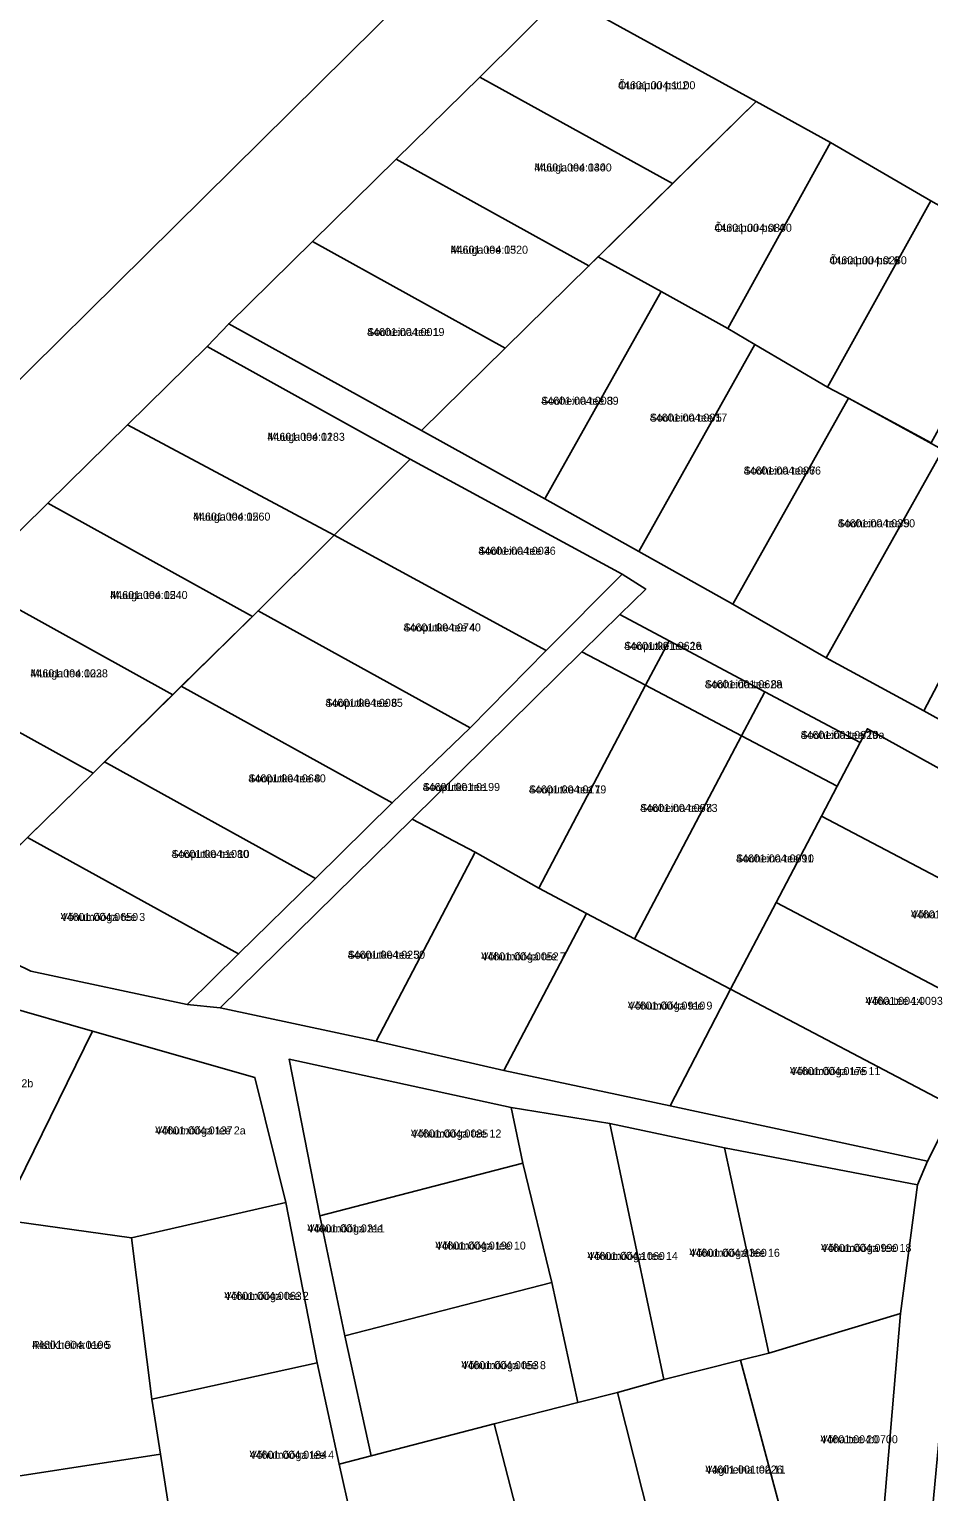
# Model space of a CAD drawing. Extents: x 551843 to 558501, y 6589003 to 6595718.
# Drawn here: x 552032.7 to 552201.2, y 6593331.6 to 6593605.7 of the extents above; entities that cross this region are included whole.
import ezdxf

# ---------------------------------------------------------------- set-up
doc = ezdxf.new("R2010")
doc.units = 0
for name, color, linetype in [('L_AADRESS', 7, 'Continuous'), ('PIIR', 7, 'Continuous'), ('TUNNUS', 7, 'Continuous')]:
    doc.layers.add(name, color=color, linetype=linetype)

msp = doc.modelspace()

# ---------------------------------------------------------------- linework, layer by layer
at = {"layer": 'PIIR'}
for points in [[(551957.32, 6593467.43), (552124.69, 6593632.88)], [(552132.56, 6593612.13), (552117.1, 6593596.73), (552101.41, 6593581.32), (552085.73, 6593565.91), (552070.04, 6593550.5), (552066, 6593546.24), (552051.07, 6593531.56), (552036.12, 6593516.88), (552021.18, 6593502.19)], [(552390.85, 6593469.35), (552373.17, 6593479.39), (552355.46, 6593489.1), (552337.59, 6593498.96), (552319.2, 6593509.13), (552282.48, 6593529.37), (552274.21, 6593533.45), (552239.65, 6593552.36), (552220.64, 6593562.81), (552201.61, 6593573.54), (552182.84, 6593584.46), (552168.9, 6593592.16), (552132.56, 6593612.13)], [(552231.31, 6593451.62), (552189.74, 6593474.62), (552188.39, 6593472.05), (552170.52, 6593481.56), (552152.58, 6593491.11), (552143.33, 6593496.01), (552148.19, 6593500.8), (552143.77, 6593503.59), (552104.07, 6593525.15), (552066, 6593546.24), (552070.04, 6593550.5), (552106.16, 6593530.52), (552129.28, 6593517.7), (552146.87, 6593507.81), (552164.48, 6593497.95), (552181.99, 6593487.89), (552200.28, 6593477.95), (552234.92, 6593458.82)], [(552015.51, 6593437.71), (552032.93, 6593429.18), (552062.25, 6593422.95), (552068.43, 6593422.31), (552097.65, 6593416.1), (552121.62, 6593410.61), (552152.74, 6593403.96), (552200.97, 6593393.62), (552199.1, 6593389.17), (552162.95, 6593396.07), (552141.49, 6593400.62), (552122.94, 6593403.65), (552081.34, 6593412.69), (552087.1, 6593383.34), (552091.81, 6593360.84), (552096.7, 6593338.37), (552090.74, 6593336.83), (552086.62, 6593355.81), (552080.74, 6593385.84), (552074.9, 6593409.27), (552044.52, 6593417.97), (552027.57, 6593422.82)]]:
    msp.add_lwpolyline(points, dxfattribs=at)
for points in [[(552153.22, 6593576.76), (552117.1, 6593596.73), (552132.56, 6593612.13), (552168.9, 6593592.16)], [(552117.1, 6593596.73), (552153.22, 6593576.76), (552137.53, 6593561.35), (552101.41, 6593581.32)], [(552182.84, 6593584.46), (552163.6, 6593549.62), (552151.05, 6593556.56), (552139.29, 6593563.05), (552168.9, 6593592.16)], [(552201.61, 6593573.54), (552182.26, 6593538.65), (552168.62, 6593546.63), (552163.6, 6593549.62), (552182.84, 6593584.46)], [(552101.41, 6593581.32), (552137.53, 6593561.35), (552121.85, 6593545.95), (552085.73, 6593565.91)], [(552220.64, 6593562.81), (552201.67, 6593528.18), (552186.19, 6593536.59), (552182.26, 6593538.65), (552201.61, 6593573.54)], [(552121.85, 6593545.95), (552106.16, 6593530.52), (552070.04, 6593550.5), (552085.73, 6593565.91)], [(552139.29, 6593563.05), (552151.05, 6593556.56), (552129.28, 6593517.7), (552106.16, 6593530.52), (552121.85, 6593545.95), (552137.53, 6593561.35)], [(552168.62, 6593546.63), (552146.87, 6593507.81), (552129.28, 6593517.7), (552151.05, 6593556.56), (552163.6, 6593549.62)], [(552104.07, 6593525.15), (552089.77, 6593510.89), (552051.07, 6593531.56), (552066, 6593546.24)], [(552168.62, 6593546.63), (552182.26, 6593538.65), (552186.19, 6593536.59), (552164.48, 6593497.95), (552146.87, 6593507.81)], [(552164.48, 6593497.95), (552186.19, 6593536.59), (552203.84, 6593526.91), (552181.99, 6593487.89)], [(552051.07, 6593531.56), (552089.77, 6593510.89), (552074.48, 6593495.68), (552036.12, 6593516.88)], [(552220.89, 6593516.92), (552219.98, 6593515.24), (552210.12, 6593496.62), (552200.28, 6593477.95), (552181.99, 6593487.89), (552203.84, 6593526.91)], [(552143.77, 6593503.59), (552129.55, 6593489.29), (552089.77, 6593510.89), (552104.07, 6593525.15)], [(552036.12, 6593516.88), (552074.48, 6593495.68), (552059.54, 6593480.99), (552021.18, 6593502.19)], [(552089.77, 6593510.89), (552129.55, 6593489.29), (552115.3, 6593474.81), (552075.55, 6593496.73)], [(552129.55, 6593489.29), (552143.77, 6593503.59), (552148.19, 6593500.8), (552143.33, 6593496.01), (552136.24, 6593489.03), (552104.42, 6593457.69), (552068.43, 6593422.31), (552062.25, 6593422.95), (552071.88, 6593432.41), (552086.29, 6593446.57), (552100.69, 6593460.73), (552115.3, 6593474.81)], [(552059.54, 6593480.99), (552044.6, 6593466.31), (552006.24, 6593487.5), (552021.18, 6593502.19)], [(552075.55, 6593496.73), (552115.3, 6593474.81), (552100.69, 6593460.73), (552061.15, 6593482.57)], [(552148.15, 6593482.78), (552136.24, 6593489.03), (552143.33, 6593496.01), (552152.58, 6593491.11)], [(552244.71, 6593477.49), (552234.92, 6593458.82), (552200.28, 6593477.95), (552210.12, 6593496.62)], [(552152.58, 6593491.11), (552170.52, 6593481.56), (552166.13, 6593473.32), (552148.15, 6593482.78)], [(552006.24, 6593487.5), (552044.6, 6593466.31), (552029.66, 6593451.62), (551991.3, 6593472.81)], [(552104.42, 6593457.69), (552136.24, 6593489.03), (552148.15, 6593482.78), (552128.14, 6593444.72), (552116.23, 6593451.49)], [(552086.29, 6593446.57), (552046.75, 6593468.41), (552061.15, 6593482.57), (552100.69, 6593460.73)], [(552148.15, 6593482.78), (552166.13, 6593473.32), (552146.11, 6593435.27), (552137.08, 6593440.02), (552128.14, 6593444.72)], [(552188.39, 6593472.05), (552184.09, 6593463.87), (552166.13, 6593473.32), (552170.52, 6593481.56)], [(552231.31, 6593451.62), (552223.17, 6593436.13), (552181.12, 6593458.23), (552184.09, 6593463.87), (552188.39, 6593472.05), (552189.74, 6593474.62)], [(552146.11, 6593435.27), (552166.13, 6593473.32), (552184.09, 6593463.87), (552181.12, 6593458.23), (552172.61, 6593442.03), (552164.07, 6593425.82)], [(552044.6, 6593466.31), (552046.75, 6593468.41), (552086.29, 6593446.57), (552071.88, 6593432.41), (552032.34, 6593454.25)], [(552068.43, 6593422.31), (552104.42, 6593457.69), (552116.23, 6593451.49), (552097.65, 6593416.1)], [(552214.65, 6593419.93), (552172.61, 6593442.03), (552181.12, 6593458.23), (552223.17, 6593436.13)], [(552062.25, 6593422.95), (552032.93, 6593429.18), (552015.51, 6593437.71), (552032.34, 6593454.25), (552071.88, 6593432.41)], [(552097.65, 6593416.1), (552116.23, 6593451.49), (552128.14, 6593444.72), (552137.08, 6593440.02), (552121.62, 6593410.61)], [(552231.31, 6593451.62), (552240.97, 6593450.32), (552231.99, 6593433.2), (552223.24, 6593416.52), (552214.49, 6593399.84), (552207.31, 6593386.18), (552206.17, 6593373.94), (552204.43, 6593355.18), (552201.95, 6593328.36), (552192.41, 6593323.77), (552195.94, 6593365.07), (552199.1, 6593389.17), (552200.97, 6593393.62), (552206.12, 6593403.72), (552214.65, 6593419.93), (552223.17, 6593436.13)], [(552214.65, 6593419.93), (552206.12, 6593403.72), (552164.07, 6593425.82), (552172.61, 6593442.03)], [(552137.08, 6593440.02), (552146.11, 6593435.27), (552164.07, 6593425.82), (552152.74, 6593403.96), (552121.62, 6593410.61)], [(552005.8, 6593432.16), (552027.57, 6593422.82), (552044.52, 6593417.97), (552027.12, 6593382.69), (551990.9, 6593401.95)], [(552164.07, 6593425.82), (552206.12, 6593403.72), (552200.97, 6593393.62), (552152.74, 6593403.96)], [(552044.52, 6593417.97), (552074.9, 6593409.27), (552080.74, 6593385.84), (552051.79, 6593379.24), (552027.12, 6593382.69)], [(552081.34, 6593412.69), (552122.94, 6593403.65), (552125.15, 6593393.19), (552087.1, 6593383.34)], [(552141.49, 6593400.62), (552151.57, 6593352.66), (552142.92, 6593350.26), (552135.46, 6593348.39), (552130.57, 6593370.86), (552125.15, 6593393.19), (552122.94, 6593403.65)], [(552162.95, 6593396.07), (552171.25, 6593357.62), (552165.92, 6593356.3), (552151.57, 6593352.66), (552141.49, 6593400.62)], [(552162.95, 6593396.07), (552199.1, 6593389.17), (552195.94, 6593365.07), (552171.25, 6593357.62)], [(552087.1, 6593383.34), (552125.15, 6593393.19), (552130.57, 6593370.86), (552091.81, 6593360.84)], [(552086.62, 6593355.81), (552055.63, 6593349), (552051.79, 6593379.24), (552080.74, 6593385.84)], [(552027.12, 6593382.69), (552051.79, 6593379.24), (552055.63, 6593349), (552057.24, 6593338.67), (552019.87, 6593332.97), (552018.18, 6593338.1), (552009.1, 6593346.19)], [(552119.8, 6593344.35), (552096.7, 6593338.37), (552091.81, 6593360.84), (552130.57, 6593370.86), (552135.46, 6593348.39)], [(552171.25, 6593357.62), (552195.94, 6593365.07), (552192.41, 6593323.77), (552175.78, 6593319.63), (552165.92, 6593356.3)], [(552055.63, 6593349), (552086.62, 6593355.81), (552090.74, 6593336.83), (552092.91, 6593327.06), (552060.18, 6593319.83), (552057.24, 6593338.67)], [(552152.17, 6593313.67), (552142.92, 6593350.26), (552151.57, 6593352.66), (552165.92, 6593356.3), (552175.78, 6593319.63)], [(552135.46, 6593348.39), (552142.92, 6593350.26), (552152.17, 6593313.67), (552129.55, 6593306.59), (552119.8, 6593344.35)], [(552096.7, 6593338.37), (552119.8, 6593344.35), (552129.55, 6593306.59), (552116.23, 6593303.16), (552092.91, 6593327.06), (552090.74, 6593336.83)], [(552019.87, 6593332.97), (552057.24, 6593338.67), (552060.18, 6593319.83), (552082.85, 6593296.1), (552035.36, 6593298.73), (552029.8, 6593302.92)]]:
    msp.add_lwpolyline(points, close=True, dxfattribs=at)

# ---------------------------------------------------------------- texts
at = {"layer": 'L_AADRESS'}
for s, p in [('Õunapuu pst 2', (552142.99, 6593594.45)), ('Muuga tee 134', (552127.31, 6593579.04)), ('Õunapuu pst 4', (552161.07, 6593567.74)), ('Muuga tee 132', (552111.62, 6593563.63)), ('Õunapuu pst 6', (552182.61, 6593561.65)), ('Sooheina tee 1', (552095.96, 6593548.21)), ('Sooheina tee 3', (552128.6, 6593535.33)), ('Sooheina tee 5', (552148.95, 6593532.17)), ('Muuga tee 128', (552077.29, 6593528.57)), ('Sooheina tee 7', (552166.53, 6593522.25)), ('Muuga tee 126', (552063.34, 6593513.62)), ('Sooheina tee 9', (552184.16, 6593512.37)), ('Sooheina tee 4', (552116.81, 6593507.22)), ('Muuga tee 124', (552047.83, 6593498.93)), ('Sooputke tee 4', (552102.79, 6593492.85)), ('Sooputke tee 1a', (552144.14, 6593489.4)), ('Muuga tee 122', (552032.88, 6593484.25)), ('Sooheina tee 8a', (552159.26, 6593482.21)), ('Sooputke tee 6', (552088.15, 6593478.73)), ('Sooheina tee 10a', (552177.21, 6593472.71)), ('Sooputke tee 8', (552073.72, 6593464.57)), ('Sooputke tee', (552106.38, 6593462.95)), ('Sooputke tee 1', (552126.29, 6593462.5)), ('Sooheina tee 8', (552147.14, 6593459.03)), ('Sooputke tee 10', (552059.32, 6593450.41)), ('Sooheina tee 10', (552165.1, 6593449.57)), ('Võha tee 12', (552197.89, 6593439.08)), ('Võhumõõga tee 3', (552038.54, 6593438.6)), ('Sooputke tee 3', (552092.33, 6593431.52)), ('Võhumõõga tee 7', (552117.36, 6593431.21)), ('Võha tee 14', (552189.36, 6593422.88)), ('Võhumõõga tee 9', (552144.84, 6593421.99)), ('Võhumõõga tee 11', (552175.21, 6593409.72)), ('Võhumõõga tee 2b', (552016.46, 6593407.43)), ('Võhumõõga tee 2a', (552056.26, 6593398.6)), ('Võhumõõga tee 12', (552104.18, 6593398.02)), ('Võhumõõga tee', (552084.77, 6593380.24)), ('Võhumõõga tee 10', (552108.75, 6593377.02)), ('Võhumõõga tee 18', (552181.03, 6593376.59)), ('Võhumõõga tee 14', (552137.25, 6593375.08)), ('Võhumõõga tee 16', (552156.37, 6593375.67)), ('Võhumõõga tee 2', (552069.2, 6593367.6)), ('Ristikheina tee 5', (552033.17, 6593358.42)), ('Võhumõõga tee 8', (552113.64, 6593354.62)), ('Võha tee 20', (552180.93, 6593340.73)), ('Võhumõõga tee 4', (552073.95, 6593337.82)), ('Vägiheina tee 11', (552159.35, 6593335.06))]:
    msp.add_text(s, height=1.5, dxfattribs=at).set_placement(p)
at = {"layer": 'TUNNUS'}
for s, p in [('44601:004:1100', (552142.99, 6593594.45)), ('44601:004:0400', (552127.31, 6593579.04)), ('44601:004:0800', (552161.07, 6593567.74)), ('44601:004:0520', (552111.62, 6593563.63)), ('44601:004:0260', (552182.61, 6593561.65)), ('44601:004:0019', (552095.96, 6593548.21)), ('44601:004:0089', (552128.6, 6593535.33)), ('44601:004:0017', (552148.95, 6593532.17)), ('44601:004:0183', (552077.29, 6593528.57)), ('44601:004:0066', (552166.53, 6593522.25)), ('44601:004:0560', (552063.34, 6593513.62)), ('44601:004:0350', (552184.16, 6593512.37)), ('44601:004:0036', (552116.81, 6593507.22)), ('44601:004:0540', (552047.83, 6593498.93)), ('44601:004:0740', (552102.79, 6593492.85)), ('44601:001:0626', (552144.14, 6593489.4)), ('44601:004:0038', (552032.88, 6593484.25)), ('44601:001:0628', (552159.26, 6593482.21)), ('44601:004:0035', (552088.15, 6593478.73)), ('44601:001:0629', (552177.21, 6593472.71)), ('44601:004:0640', (552073.72, 6593464.57)), ('44601:001:0199', (552106.38, 6593462.95)), ('44601:004:0179', (552126.29, 6593462.5)), ('44601:004:0073', (552147.14, 6593459.03)), ('44601:004:1080', (552059.32, 6593450.41)), ('44601:004:0091', (552165.1, 6593449.57)), ('44601:004:0043', (552197.89, 6593439.08)), ('44601:004:0650', (552038.54, 6593438.6)), ('44601:004:0250', (552092.33, 6593431.52)), ('44601:004:0052', (552117.36, 6593431.21)), ('44601:004:0093', (552189.36, 6593422.88)), ('44601:004:0910', (552144.84, 6593421.99)), ('44601:004:0175', (552175.21, 6593409.72)), ('44601:004:0137', (552056.26, 6593398.6)), ('44601:004:0085', (552104.18, 6593398.02)), ('44601:001:0211', (552084.77, 6593380.24)), ('44601:004:0190', (552108.75, 6593377.02)), ('44601:004:0990', (552181.03, 6593376.59)), ('44601:004:1060', (552137.25, 6593375.08)), ('44601:004:0360', (552156.37, 6593375.67)), ('44601:004:0063', (552069.2, 6593367.6)), ('44601:004:0106', (552033.17, 6593358.42)), ('44601:004:0053', (552113.64, 6593354.62)), ('44601:004:0700', (552180.93, 6593340.73)), ('44601:004:0184', (552073.95, 6593337.82)), ('44601:001:0226', (552159.35, 6593335.06))]:
    msp.add_text(s, height=1.5, dxfattribs=at).set_placement(p)

doc.saveas('drawing.dxf')
